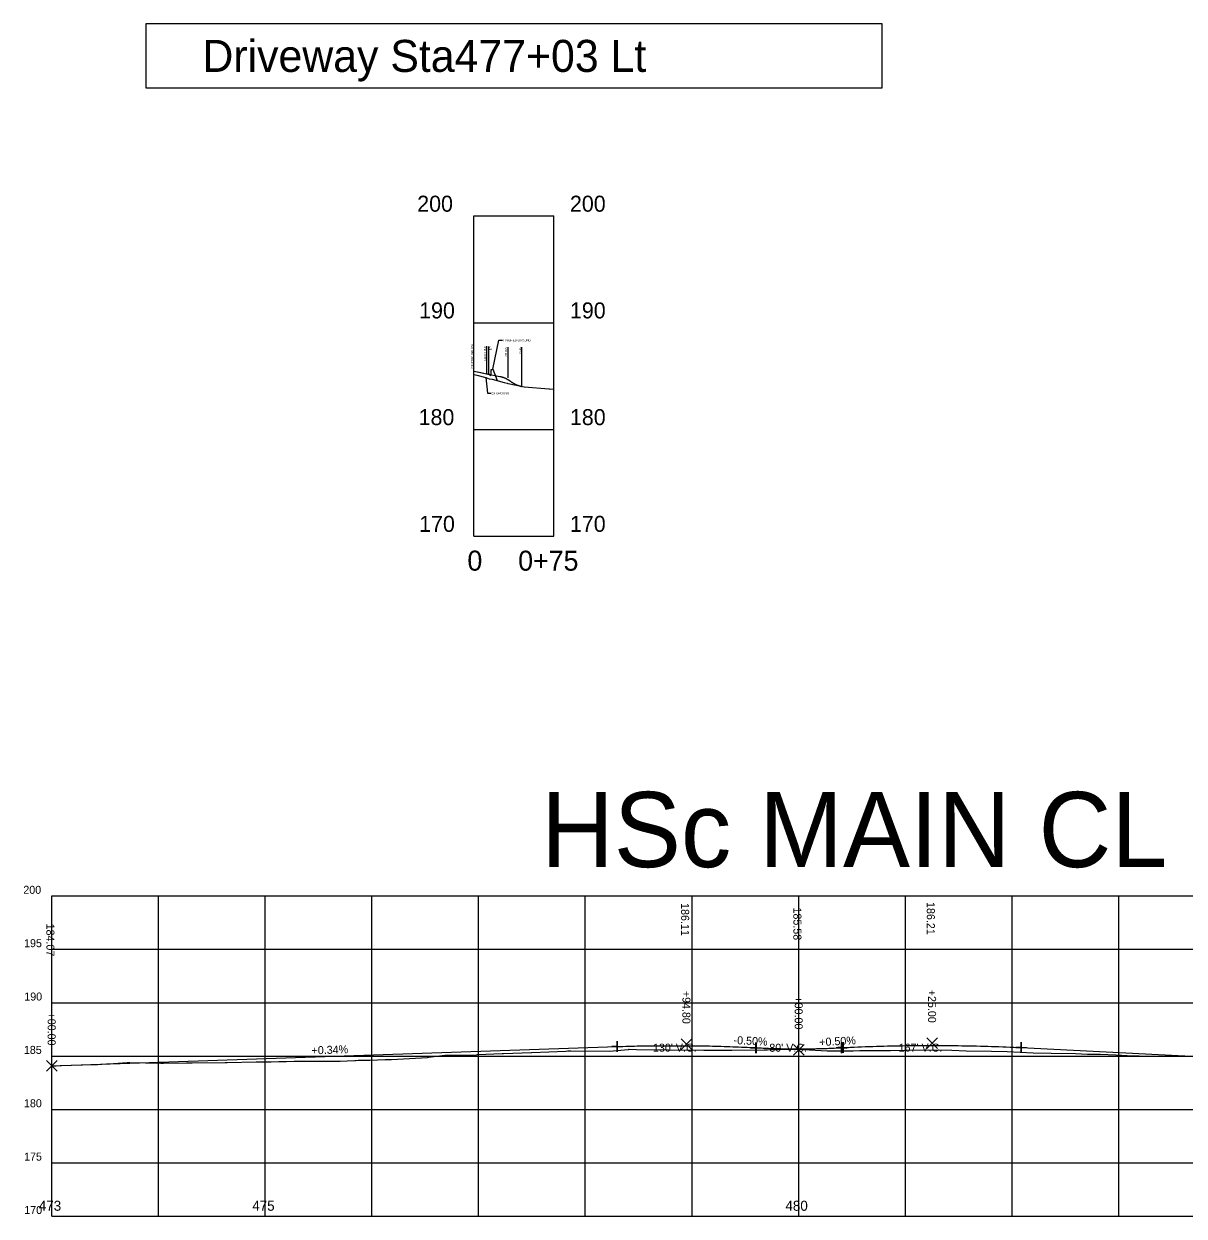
# Model space of a CAD drawing. Extents: x 7585489 to 7587427, y 550013 to 552072.
# Drawn here: x 7585532 to 7586620, y 550954 to 552072 of the extents above; entities that cross this region are included whole.
import ezdxf

# ---------------------------------------------------------------- set-up
doc = ezdxf.new("R2010")
doc.units = 0
for name, color, linetype in [('E_RDWY_PROF_Ground', 7, 'Continuous'), ('P_RDWY_PROF_Align', 7, 'Continuous'), ('P_RDWY_PROF_AlignTx', 7, 'Continuous'), ('P_RDWY_PROF_General', 7, 'Continuous'), ('P_RDWY_PROF_GeneralTx', 7, 'Continuous'), ('P_RDWY_PROF_Grid', 7, 'Continuous'), ('P_RDWY_PROF_GridTx', 7, 'Continuous'), ('P_RDWY_ROAD_Approach', 7, 'Continuous'), ('P_RDWY_ROAD_EdgeAsph', 7, 'Continuous'), ('P_RDWY_ROAD_Laneline', 7, 'Continuous')]:
    doc.layers.add(name, color=color, linetype=linetype)

msp = doc.modelspace()

# ---------------------------------------------------------------- linework, layer by layer
for points in [[(7586088.2, 551113.1), (7586088.2, 551118.1), (7586088.2, 551113.1), (7586083.2, 551113.1), (7586088.2, 551113.1), (7586088.2, 551108.1), (7586088.2, 551113.1), (7586093.2, 551113.1)], [(7586218.4, 551112.1), (7586218.4, 551117.1), (7586218.4, 551112.1), (7586213.4, 551112.1), (7586218.4, 551112.1), (7586218.4, 551107.1), (7586218.4, 551112.1), (7586223.4, 551112.1)], [(7586299.9, 551112.2), (7586299.9, 551117.2), (7586299.9, 551112.2), (7586294.9, 551112.2), (7586299.9, 551112.2), (7586299.9, 551107.2), (7586299.9, 551112.2), (7586304.9, 551112.2)]]:
    msp.add_lwpolyline(points)
at = {"layer": 'E_RDWY_PROF_Ground'}
for points in [[(7585954, 551743.1), (7585954.3, 551743.1), (7585956.6, 551742.4), (7585965.2, 551740.1), (7585968.2, 551738.9), (7585971.2, 551738.6), (7585982.3, 551735.6), (7585985.2, 551734.7), (7585985.7, 551734.4), (7585986, 551734.4), (7586001, 551731.3), (7586001.5, 551731.3), (7586001.5, 551731.3), (7586024.2, 551729.5), (7586024.8, 551729.4), (7586024.9, 551729.4), (7586029, 551729.1)], [(7585965.2, 551740.1), (7585966.8, 551725.3), (7585969.9, 551725.3)], [(7585558.4, 551095), (7585562.5, 551095.1), (7585566.2, 551095.4), (7585598, 551096.3), (7585601.2, 551096.3), (7585609.6, 551097), (7585611.8, 551097.1), (7585629, 551098.1), (7585631.6, 551098.2), (7585660.8, 551097.6), (7585663.1, 551097.5), (7585684.6, 551097.9), (7585687.6, 551097.9), (7585690, 551097.9), (7585720.9, 551098.2), (7585722.8, 551098.3), (7585749.9, 551098.9), (7585750.7, 551098.9), (7585753.5, 551098.9), (7585757, 551098.9), (7585764.1, 551099), (7585771.3, 551099.2), (7585778.4, 551099.3), (7585785.5, 551099.4), (7585789.2, 551099.5), (7585792.6, 551099.5), (7585792.7, 551099.5), (7585795.5, 551099.6), (7585799.7, 551099.6), (7585806.8, 551099.5), (7585813.9, 551099.5), (7585821, 551099.5), (7585826.3, 551099.4), (7585828.1, 551099.5), (7585828.8, 551099.5), (7585835.2, 551099.8), (7585842.3, 551100.2), (7585843.5, 551100.2), (7585845.5, 551100.3), (7585849.4, 551100.4), (7585856.6, 551100.5), (7585863.7, 551100.7), (7585870.8, 551100.9), (7585875, 551101), (7585876.8, 551101), (7585910.4, 551103), (7585911.5, 551103.1), (7585926.8, 551105), (7585956.4, 551105.5), (7585957.5, 551105.6), (7585980.6, 551106.7), (7585981.7, 551106.8), (7585981.8, 551106.8), (7586008.1, 551107.7), (7586008.3, 551107.7), (7586040.2, 551108.9), (7586042, 551109.1), (7586044.8, 551109.2), (7586080.6, 551109), (7586098.9, 551110.5), (7586099.6, 551110.6), (7586106.5, 551110.5), (7586135.7, 551110.1), (7586136.3, 551110.1), (7586169.3, 551109.8), (7586171, 551109.7), (7586193.8, 551109.7), (7586195.8, 551109.8), (7586225.9, 551110.2), (7586229.2, 551110.2), (7586251.1, 551110.6), (7586257.6, 551110.6), (7586285, 551109.3), (7586293.2, 551109.1), (7586309.4, 551109.3), (7586315.7, 551109.5), (7586344.5, 551109.5), (7586357.5, 551109.8), (7586380.3, 551110.2), (7586401.9, 551109.7), (7586415.3, 551109.3), (7586438.9, 551108.9), (7586453.8, 551108.5), (7586478.1, 551107.4), (7586494.9, 551107.1), (7586517.8, 551106.6), (7586528.9, 551106.1), (7586540.8, 551105.9), (7586555.5, 551105.4), (7586566.2, 551104.7), (7586588.9, 551104.3), (7586606.9, 551104.1), (7586629.2, 551103.9)]]:
    msp.add_lwpolyline(points, dxfattribs=at)
at = {"layer": 'P_RDWY_PROF_Align'}
for p, q in [((7585954, 551746.1), (7585966, 551743.7)), ((7585966, 551743.7), (7585978.2, 551741.2)), ((7585998.8, 551731.8), (7585999, 551731.7)), ((7585558.4, 551095), (7586088.2, 551113.1)), ((7586218.2, 551112.1), (7586218.4, 551112.1)), ((7586298.4, 551112.1), (7586299.9, 551112.2)), ((7586466.9, 551112.2), (7587187.7, 551076.1))]:
    msp.add_line(p, q, dxfattribs=at)
for points in [[(7585971.6, 551747.8), (7585977.4, 551775.1), (7585980.9, 551775.1)], [(7585954, 551746.1), (7585958.8, 551745.1), (7585966, 551743.7), (7585967.2, 551743.4), (7585968, 551743.3), (7585968.8, 551742.6), (7585970, 551741.7), (7585970.1, 551745.2), (7585970.1, 551747.5), (7585970.3, 551747.5), (7585970.6, 551747.6), (7585971.2, 551747.7), (7585971.6, 551747.8), (7585973.2, 551743.8), (7585975.9, 551737.2)], [(7585978.2, 551741.2), (7585978.5, 551741.2), (7585978.7, 551741.1), (7585978.9, 551741.1), (7585979.1, 551741), (7585979.3, 551741), (7585979.5, 551740.9), (7585979.7, 551740.9), (7585979.9, 551740.8), (7585980.1, 551740.8), (7585980.3, 551740.7), (7585980.5, 551740.6), (7585980.7, 551740.6), (7585981, 551740.5), (7585981.2, 551740.4), (7585981.4, 551740.4), (7585981.6, 551740.3), (7585981.8, 551740.2), (7585982, 551740.1), (7585982.2, 551740), (7585982.4, 551739.9), (7585982.6, 551739.9), (7585982.8, 551739.8), (7585983, 551739.7), (7585983.5, 551739.5), (7585983.7, 551739.4), (7585983.9, 551739.3), (7585984.1, 551739.2), (7585984.3, 551739.1), (7585984.5, 551739), (7585984.7, 551738.9), (7585984.9, 551738.7), (7585985.1, 551738.6), (7585985.3, 551738.5), (7585985.5, 551738.4), (7585985.7, 551738.3), (7585986, 551738.2), (7585986.2, 551738), (7585986.4, 551737.9), (7585986.6, 551737.8), (7585986.8, 551737.6), (7585987, 551737.5), (7585987.2, 551737.4), (7585987.4, 551737.2), (7585987.6, 551737.1), (7585987.8, 551736.9), (7585988, 551736.8), (7585988.2, 551736.6)], [(7585988.2, 551736.6), (7585988.5, 551736.5), (7585988.7, 551736.3), (7585988.9, 551736.2), (7585989.1, 551736), (7585989.3, 551735.9), (7585989.6, 551735.7), (7585989.8, 551735.6), (7585990, 551735.5), (7585990.2, 551735.3), (7585990.4, 551735.2), (7585990.7, 551735.1), (7585990.9, 551734.9), (7585991.1, 551734.8), (7585991.3, 551734.7), (7585991.5, 551734.5), (7585991.8, 551734.4), (7585992, 551734.3), (7585992.2, 551734.2), (7585992.4, 551734.1), (7585992.6, 551734), (7585992.9, 551733.9), (7585993.1, 551733.7), (7585993.3, 551733.6), (7585993.7, 551733.4), (7585994, 551733.3), (7585994.2, 551733.3), (7585994.4, 551733.2), (7585994.6, 551733.1), (7585994.8, 551733), (7585995, 551732.9), (7585995.3, 551732.8), (7585995.5, 551732.7), (7585995.7, 551732.7), (7585995.9, 551732.6), (7585996.1, 551732.5), (7585996.4, 551732.4), (7585996.6, 551732.4), (7585996.8, 551732.3), (7585997, 551732.2), (7585997.2, 551732.2), (7585997.5, 551732.1), (7585997.7, 551732.1), (7585997.9, 551732), (7585998.1, 551731.9), (7585998.3, 551731.9), (7585998.6, 551731.8), (7585998.8, 551731.8)], [(7586088.2, 551113.1), (7586090.9, 551113.2), (7586093.6, 551113.3), (7586096.3, 551113.4), (7586099, 551113.5), (7586101.7, 551113.5), (7586104.4, 551113.6), (7586107.1, 551113.7), (7586109.8, 551113.7), (7586112.5, 551113.8), (7586115.2, 551113.8), (7586117.9, 551113.9), (7586120.7, 551113.9), (7586123.4, 551113.9), (7586126.1, 551114), (7586128.8, 551114), (7586131.5, 551114), (7586134.2, 551114), (7586136.9, 551114), (7586139.6, 551114), (7586142.3, 551114), (7586145, 551114), (7586147.7, 551114), (7586150.4, 551114), (7586155.9, 551114), (7586158.6, 551113.9), (7586161.3, 551113.9), (7586164, 551113.9), (7586166.7, 551113.8), (7586169.4, 551113.8), (7586172.1, 551113.7), (7586174.8, 551113.7), (7586177.5, 551113.6), (7586180.2, 551113.5), (7586182.9, 551113.5), (7586185.7, 551113.4), (7586188.4, 551113.3), (7586191.1, 551113.2), (7586193.8, 551113.1), (7586196.5, 551113), (7586199.2, 551112.9), (7586201.9, 551112.8), (7586204.6, 551112.7), (7586207.3, 551112.6), (7586210, 551112.5), (7586212.7, 551112.4), (7586215.4, 551112.2), (7586218.2, 551112.1)], [(7586153.2, 551115.3), (7586148.2, 551120.3), (7586153.2, 551115.3), (7586148.2, 551110.3), (7586153.2, 551115.3), (7586158.2, 551110.3), (7586153.2, 551115.3), (7586158.2, 551120.3)], [(7586218.2, 551112.1), (7586218.2, 551117.1), (7586218.2, 551112.1), (7586213.2, 551112.1), (7586218.2, 551112.1), (7586218.2, 551107.1), (7586218.2, 551112.1), (7586223.2, 551112.1)], [(7586258.4, 551110.1), (7586253.4, 551115.1), (7586258.4, 551110.1), (7586253.4, 551105.1), (7586258.4, 551110.1), (7586263.4, 551105.1), (7586258.4, 551110.1), (7586263.4, 551115.1)], [(7586298.4, 551112.1), (7586298.4, 551117.1), (7586298.4, 551112.1), (7586293.4, 551112.1), (7586298.4, 551112.1), (7586298.4, 551107.1), (7586298.4, 551112.1), (7586303.4, 551112.1)], [(7586299.9, 551112.2), (7586303.3, 551112.3), (7586306.8, 551112.5), (7586310.3, 551112.7), (7586313.8, 551112.8), (7586317.2, 551112.9), (7586320.7, 551113.1), (7586324.2, 551113.2), (7586327.7, 551113.3), (7586331.2, 551113.4), (7586334.6, 551113.5), (7586338.1, 551113.6), (7586341.6, 551113.7), (7586345.1, 551113.8), (7586348.6, 551113.9), (7586352, 551114), (7586355.5, 551114), (7586359, 551114.1), (7586362.5, 551114.1), (7586366, 551114.2), (7586369.4, 551114.2), (7586372.9, 551114.2), (7586376.4, 551114.2), (7586379.9, 551114.2), (7586386.8, 551114.2), (7586390.3, 551114.2), (7586393.8, 551114.2), (7586397.3, 551114.2), (7586400.7, 551114.2), (7586404.2, 551114.1), (7586407.7, 551114.1), (7586411.2, 551114), (7586414.7, 551114), (7586418.1, 551113.9), (7586421.6, 551113.8), (7586425.1, 551113.7), (7586428.6, 551113.6), (7586432.1, 551113.5), (7586435.5, 551113.4), (7586439, 551113.3), (7586442.5, 551113.2), (7586446, 551113.1), (7586449.5, 551112.9), (7586452.9, 551112.8), (7586456.4, 551112.7), (7586459.9, 551112.5), (7586463.4, 551112.3), (7586466.9, 551112.2)], [(7586383.4, 551116.3), (7586378.4, 551121.3), (7586383.4, 551116.3), (7586378.4, 551111.3), (7586383.4, 551116.3), (7586388.4, 551111.3), (7586383.4, 551116.3), (7586388.4, 551121.3)], [(7586466.9, 551112.2), (7586466.9, 551117.2), (7586466.9, 551112.2), (7586461.9, 551112.2), (7586466.9, 551112.2), (7586466.9, 551107.2), (7586466.9, 551112.2), (7586471.9, 551112.2)], [(7586218.4, 551112.1), (7586220, 551112), (7586221.7, 551111.9), (7586223.4, 551111.9), (7586225, 551111.8), (7586226.7, 551111.7), (7586228.4, 551111.6), (7586230, 551111.6), (7586231.7, 551111.5), (7586233.4, 551111.5), (7586235, 551111.4), (7586236.7, 551111.4), (7586238.4, 551111.3), (7586240, 551111.3), (7586241.7, 551111.3), (7586243.4, 551111.2), (7586245, 551111.2), (7586246.7, 551111.2), (7586248.4, 551111.1), (7586250, 551111.1), (7586251.7, 551111.1), (7586253.4, 551111.1), (7586255, 551111.1), (7586256.7, 551111.1), (7586260, 551111.1), (7586261.7, 551111.1), (7586263.4, 551111.1), (7586265, 551111.1), (7586266.7, 551111.1), (7586268.4, 551111.1), (7586270, 551111.2), (7586271.7, 551111.2), (7586273.4, 551111.2), (7586275, 551111.3), (7586276.7, 551111.3), (7586278.4, 551111.3), (7586280, 551111.4), (7586281.7, 551111.4), (7586283.4, 551111.5), (7586285, 551111.5), (7586286.7, 551111.6), (7586288.4, 551111.6), (7586290, 551111.7), (7586291.7, 551111.8), (7586293.4, 551111.9), (7586295, 551111.9), (7586296.7, 551112), (7586298.4, 551112.1)], [(7585558.4, 551095), (7585553.4, 551100), (7585558.4, 551095), (7585553.4, 551090), (7585558.4, 551095), (7585563.4, 551090), (7585558.4, 551095), (7585563.4, 551100)]]:
    msp.add_lwpolyline(points, dxfattribs=at)
at = {"layer": 'P_RDWY_PROF_General'}
msp.add_lwpolyline([(7586336.5, 552071.5), (7585646.5, 552071.5), (7585646.5, 552011.5), (7586336.5, 552011.5)], close=True, dxfattribs=at)
at = {"layer": 'P_RDWY_PROF_Grid'}
for p, q in [((7585954, 551591.5), (7585954, 551891.5)), ((7585954, 551891.5), (7586029, 551891.5)), ((7585954, 551891.5), (7586029, 551891.5)), ((7586029, 551591.5), (7586029, 551891.5)), ((7585954, 551791.5), (7586029, 551791.5)), ((7585954, 551691.5), (7586029, 551691.5)), ((7585954, 551591.5), (7586029, 551591.5)), ((7585558.4, 550954.3), (7585558.4, 551254.3)), ((7585558.4, 551254.3), (7587403.4, 551254.3)), ((7585558.4, 551254.3), (7587403.4, 551254.3)), ((7585658.4, 550954.3), (7585658.4, 551254.3)), ((7585758.4, 550954.3), (7585758.4, 551254.3)), ((7585858.4, 550954.3), (7585858.4, 551254.3)), ((7585958.4, 550954.3), (7585958.4, 551254.3)), ((7586058.4, 550954.3), (7586058.4, 551254.3)), ((7586158.4, 550954.3), (7586158.4, 551254.3)), ((7586258.4, 550954.3), (7586258.4, 551254.3)), ((7586358.4, 550954.3), (7586358.4, 551254.3)), ((7586458.4, 550954.3), (7586458.4, 551254.3)), ((7586558.4, 550954.3), (7586558.4, 551254.3)), ((7585558.4, 551204.3), (7587403.4, 551204.3)), ((7585558.4, 551154.3), (7587403.4, 551154.3)), ((7585558.4, 551104.3), (7587403.4, 551104.3)), ((7585558.4, 551054.3), (7587403.4, 551054.3)), ((7585558.4, 551004.3), (7587403.4, 551004.3)), ((7585558.4, 550954.3), (7587403.4, 550954.3))]:
    msp.add_line(p, q, dxfattribs=at)
at = {"layer": 'P_RDWY_PROF_GridTx'}
for p, q in [((7585658.4, 550954.3), (7585658.4, 550964.3)), ((7585858.4, 550954.3), (7585858.4, 550964.3)), ((7585958.4, 550954.3), (7585958.4, 550964.3)), ((7586058.4, 550954.3), (7586058.4, 550964.3)), ((7586158.4, 550954.3), (7586158.4, 550964.3)), ((7586358.4, 550954.3), (7586358.4, 550964.3)), ((7586458.4, 550954.3), (7586458.4, 550964.3)), ((7586558.4, 550954.3), (7586558.4, 550964.3))]:
    msp.add_line(p, q, dxfattribs=at)
at = {"layer": 'P_RDWY_ROAD_Approach'}
for p, q in [((7585966, 551743.7), (7585966, 551769.6)), ((7585986, 551739.7), (7585986, 551768.6)), ((7585999, 551731.7), (7585999, 551768.6))]:
    msp.add_line(p, q, dxfattribs=at)
at = {"layer": 'P_RDWY_ROAD_EdgeAsph'}
msp.add_line((7585968, 551743.3), (7585968, 551769.2), dxfattribs=at)
msp.add_lwpolyline([(7585968, 551743.3), (7585968, 551743.5), (7585968, 551743.3), (7585967.8, 551743.3), (7585968, 551743.3), (7585968, 551743), (7585968, 551743.3), (7585968.3, 551743.3)], dxfattribs=at)
at = {"layer": 'P_RDWY_ROAD_Laneline'}
msp.add_lwpolyline([(7585966, 551743.7), (7585966, 551743.9), (7585966, 551743.7), (7585965.8, 551743.7), (7585966, 551743.7), (7585966, 551743.4), (7585966, 551743.7), (7585966.3, 551743.7)], dxfattribs=at)

# ---------------------------------------------------------------- texts
at = {"layer": 'E_RDWY_PROF_Ground'}
msp.add_text('EX GROUND', height=2, dxfattribs=at).set_placement((7585970.4, 551724.3))
at = {"layer": 'P_RDWY_PROF_Align'}
msp.add_text('FINISHED GROUND', height=2, dxfattribs=at).set_placement((7585981.3, 551774))
at = {"layer": 'P_RDWY_PROF_AlignTx'}
for s, rotation, p in [('186.11                              ', 270, (7586148.2, 551247.6)), ('186.21                              ', 270, (7586378.4, 551248.6)), ('185.58                              ', 270, (7586253.4, 551243.5)), ('184.07                              ', 270, (7585553.4, 551228.4)), ('                              +94.80', 270, (7586149.4, 551249)), ('                              +00.00', 270, (7586254.6, 551243.8)), ('                              +25.00', 270, (7586379.6, 551250)), ('                              +00.00', 270, (7585554.6, 551228.7)), ('+0.34%', 1.9595, (7585802, 551105.8)), ('-0.50%', 357.1376, (7586197.2, 551115.6)), ('+0.50%', 2.8624, (7586277.8, 551113.6))]:
    msp.add_text(s, height=7.5, rotation=rotation, dxfattribs=at).set_placement(p)
for s, p in [("130' V.C.", (7586121.8, 551108.4)), ("80' V.C.", (7586230.8, 551108.3)), ("167' V.C.", (7586352, 551108.4))]:
    msp.add_text(s, height=7.5, dxfattribs=at).set_placement(p)
at = {"layer": 'P_RDWY_PROF_GeneralTx'}
for s, height, p in [('Driveway Sta477+03 Lt', 30, (7585699.6, 552026.5)), ('HSc MAIN CL', 70.5, (7586017, 551281.3))]:
    msp.add_text(s, height=height, dxfattribs=at).set_placement(p)
at = {"layer": 'P_RDWY_PROF_GridTx'}
for s, height, p in [('200', 15, (7585900.9, 551895.5)), ('200', 15, (7585900.9, 551895.5)), ('200', 15, (7586044, 551895.5)), ('200', 15, (7586044, 551895.5)), ('190', 15, (7585902.7, 551795.5)), ('190', 15, (7586044, 551795.5)), ('180', 15, (7585902.2, 551695.5)), ('180', 15, (7586044, 551695.5)), ('170', 15, (7585902.7, 551595.5)), ('170', 15, (7586044, 551595.5)), ('0', 18.8, (7585947.9, 551559.1)), ('0+75', 18.75, (7585995.5, 551559.1)), ('200', 7.5, (7585531.8, 551256.3)), ('200', 7.5, (7585531.8, 551256.3)), ('195', 7.5, (7585532.5, 551206.3)), ('190', 7.5, (7585532.7, 551156.3)), ('185', 7.5, (7585532.3, 551106.3)), ('180', 7.5, (7585532.4, 551056.3)), ('175', 7.5, (7585532.5, 551006.3)), ('473', 9.4, (7585546.3, 550959.3)), ('475', 9.4, (7585746.3, 550959.3)), ('480', 9.4, (7586245.9, 550959.3)), ('170', 7.5, (7585532.7, 550956.3))]:
    msp.add_text(s, height=height, dxfattribs=at).set_placement(p)
at = {"layer": 'P_RDWY_ROAD_Approach'}
for s, p in [('CENTERLINE HSc', (7585953.3, 551748.6)), ('LANE LINE', (7585965.5, 551755.5)), ("20' O/S", (7585985.1, 551759.6)), ('0+45', (7585998.5, 551762.4))]:
    msp.add_text(s, height=2, rotation=90, dxfattribs=at).set_placement(p)
at = {"layer": 'P_RDWY_ROAD_EdgeAsph'}
msp.add_text('EP', height=2, rotation=90, dxfattribs=at).set_placement((7585970.6, 551765.6))

doc.saveas('drawing.dxf')
